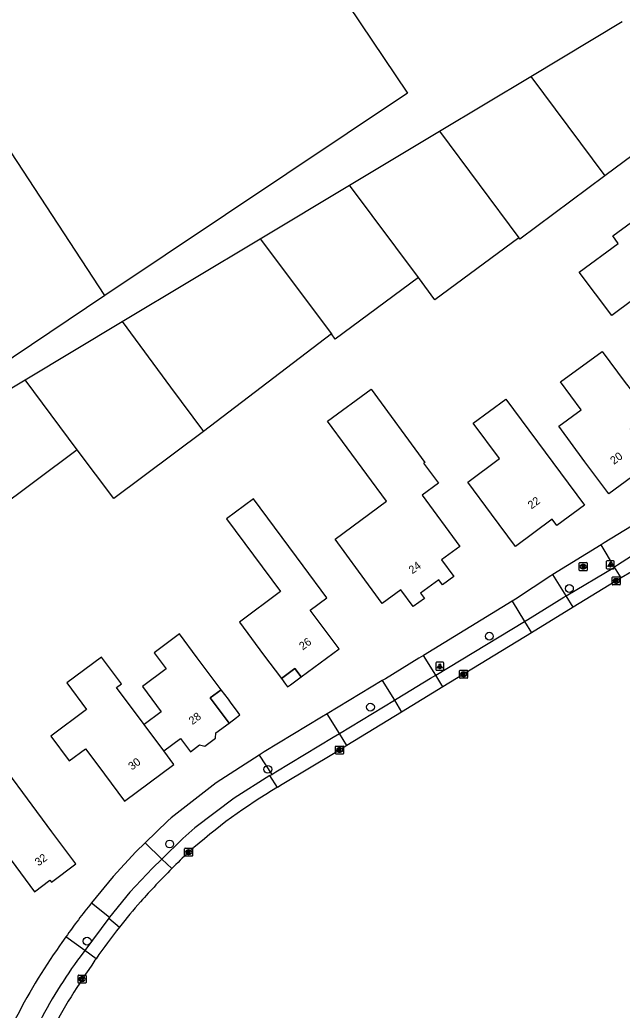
# Model space of a CAD drawing. Extents: x 156651 to 158072, y 387631 to 388990.
# Drawn here: x 157423.6 to 157498.9, y 387781.5 to 387905.3 of the extents above; entities that cross this region are included whole.
import ezdxf

# ---------------------------------------------------------------- set-up
doc = ezdxf.new("R2010")
doc.units = 0
for name, color, linetype in [('IMGEO_Boom', 7, 'Continuous'), ('IMGEO_Brandkraan', 7, 'Continuous'), ('IMGEO_Kolk', 7, 'Continuous'), ('IMGEO_Lichtpunt', 7, 'Continuous'), ('IMGEO_Pand', 7, 'Continuous'), ('IMGEO_Pand_nummerreeks', 7, 'Continuous'), ('IMGEO_Pand_overbouw', 7, 'Continuous'), ('IMGEO_Rijbaan_lokaal_open', 7, 'Continuous'), ('IMGEO_Voetpad_open', 7, 'Continuous')]:
    doc.layers.add(name, color=color, linetype=linetype)

msp = doc.modelspace()

# ---------------------------------------------------------------- linework, layer by layer
at = {"layer": 'IMGEO_Boom'}
for centre in [(157492.26, 387834.21), (157482.27, 387828.25), (157467.42, 387819.39), (157454.6, 387811.62), (157442.35, 387802.29), (157432.04, 387790.15)]:
    msp.add_circle(centre, 0.489, dxfattribs=at)
at = {"layer": 'IMGEO_Brandkraan'}
for p, q in [((157493.48, 387836.52), (157493.48, 387837.37)), ((157493.56, 387837.44), (157494.41, 387837.44)), ((157494.41, 387836.44), (157493.56, 387836.44)), ((157493.97, 387837.22), (157494, 387837.22)), ((157493.99, 387836.66), (157493.97, 387836.66)), ((157494.48, 387837.37), (157494.48, 387836.52))]:
    msp.add_line(p, q, dxfattribs=at)
for points in [[(157493.48, 387836.52), (157493.48, 387837.37)], [(157493.56, 387837.44), (157494.41, 387837.44)], [(157494.41, 387836.44), (157493.56, 387836.44)], [(157493.83, 387837.14), (157493.83, 387836.74), (157494.04, 387836.74)], [(157494.06, 387837.14), (157493.83, 387837.14)], [(157494.01, 387837.06), (157493.96, 387837.06), (157493.96, 387836.98)], [(157493.96, 387836.98), (157494.01, 387836.98)], [(157494.02, 387836.91), (157493.96, 387836.91), (157493.96, 387836.83)], [(157493.96, 387836.83), (157494.02, 387836.83)], [(157494.48, 387837.37), (157494.48, 387836.52)]]:
    msp.add_lwpolyline(points, dxfattribs=at)
for centre, radius, start, end in [((157493.56, 387837.37), 0.0765, 91.552, 178.448), ((157493.56, 387837.37), 0.0765, 91.552, 178.448), ((157493.56, 387836.52), 0.0765, 181.552, 268.448), ((157493.56, 387836.52), 0.0765, 181.552, 268.448), ((157494.01, 387837.02), 0.0379, 267.8285, 90.9355), ((157494.02, 387836.87), 0.0404, 269.8759, 90.5077), ((157494.05, 387836.99), 0.251, 268.6676, 293.5347), ((157494.07, 387837), 0.145, 59.4692, 91.5367), ((157494.09, 387837.04), 0.0922, 285.5137, 58.1501), ((157494.1, 387836.85), 0.105, 301.3115, 78.989), ((157494.41, 387837.37), 0.0765, 1.552, 88.448), ((157494.41, 387837.37), 0.0765, 1.552, 88.448), ((157494.41, 387836.52), 0.0765, 271.552, 358.448), ((157494.41, 387836.52), 0.0765, 271.552, 358.448)]:
    msp.add_arc(centre, radius, start, end, dxfattribs=at)
for centre, major_axis, ratio, start_param, end_param in [((157493.97, 387836.94), (-0.387, 0.002), 0.722429, 4.712389, 7.853982), ((157493.99, 387836.94), (-0.39, 0.002), 0.717154, 1.570796, 4.712389)]:
    msp.add_ellipse(centre, major_axis=major_axis, ratio=ratio, start_param=start_param, end_param=end_param, dxfattribs=at)
at = {"layer": 'IMGEO_Kolk'}
for p, q in [((157497.62, 387834.74), (157497.62, 387835.59)), ((157497.69, 387835.67), (157498.54, 387835.67)), ((157498.11, 387835.44), (157498.13, 387835.44)), ((157498.62, 387835.59), (157498.62, 387834.74)), ((157498.54, 387834.66), (157497.69, 387834.66)), ((157498.13, 387834.89), (157498.1, 387834.89)), ((157478.55, 387823.08), (157478.55, 387823.93)), ((157478.63, 387824), (157479.48, 387824)), ((157479.55, 387823.93), (157479.55, 387823.08)), ((157479.48, 387823), (157478.63, 387823)), ((157479.04, 387823.78), (157479.06, 387823.78)), ((157479.06, 387823.22), (157479.04, 387823.22)), ((157463.07, 387813.61), (157463.07, 387814.46)), ((157463.14, 387814.53), (157463.99, 387814.53)), ((157463.55, 387814.31), (157463.58, 387814.31)), ((157464.07, 387814.46), (157464.07, 387813.61)), ((157463.99, 387813.53), (157463.14, 387813.53)), ((157463.58, 387813.75), (157463.55, 387813.75)), ((157444.22, 387800.85), (157444.22, 387801.7)), ((157444.3, 387801.77), (157445.15, 387801.77)), ((157445.22, 387801.7), (157445.22, 387800.85)), ((157445.15, 387800.77), (157444.3, 387800.77)), ((157444.71, 387801.55), (157444.73, 387801.55)), ((157444.73, 387800.99), (157444.71, 387800.99)), ((157430.91, 387784.99), (157430.91, 387785.84)), ((157430.98, 387785.91), (157431.83, 387785.91)), ((157431.39, 387785.69), (157431.42, 387785.69)), ((157431.91, 387785.84), (157431.91, 387784.99)), ((157431.83, 387784.91), (157430.98, 387784.91)), ((157431.42, 387785.13), (157431.39, 387785.13))]:
    msp.add_line(p, q, dxfattribs=at)
for points in [[(157497.62, 387834.74), (157497.62, 387835.59)], [(157497.69, 387835.67), (157498.54, 387835.67)], [(157497.94, 387835.36), (157498.06, 387835.36), (157498.06, 387835.21), (157498.19, 387835.36), (157498.36, 387835.36), (157498.21, 387835.21), (157498.36, 387834.96), (157498.21, 387834.96), (157498.13, 387835.13), (157498.06, 387835.06), (157498.06, 387834.96), (157497.94, 387834.96), (157497.94, 387835.36)], [(157498.62, 387835.59), (157498.62, 387834.74)], [(157498.54, 387834.66), (157497.69, 387834.66)], [(157478.55, 387823.08), (157478.55, 387823.93)], [(157478.63, 387824), (157479.48, 387824)], [(157479.55, 387823.93), (157479.55, 387823.08)], [(157479.48, 387823), (157478.63, 387823)], [(157478.87, 387823.7), (157479, 387823.7), (157479, 387823.55), (157479.12, 387823.7), (157479.29, 387823.7), (157479.14, 387823.55), (157479.3, 387823.3), (157479.14, 387823.3), (157479.06, 387823.47), (157479, 387823.4), (157479, 387823.3), (157478.87, 387823.3), (157478.87, 387823.7)], [(157463.07, 387813.61), (157463.07, 387814.46)], [(157463.14, 387814.53), (157463.99, 387814.53)], [(157463.39, 387814.23), (157463.51, 387814.23), (157463.51, 387814.08), (157463.64, 387814.23), (157463.8, 387814.23), (157463.66, 387814.08), (157463.81, 387813.83), (157463.66, 387813.83), (157463.57, 387814), (157463.51, 387813.93), (157463.51, 387813.83), (157463.39, 387813.83), (157463.39, 387814.23)], [(157464.07, 387814.46), (157464.07, 387813.61)], [(157463.99, 387813.53), (157463.14, 387813.53)], [(157444.22, 387800.85), (157444.22, 387801.7)], [(157444.3, 387801.77), (157445.15, 387801.77)], [(157445.22, 387801.7), (157445.22, 387800.85)], [(157445.15, 387800.77), (157444.3, 387800.77)], [(157444.54, 387801.47), (157444.67, 387801.47), (157444.67, 387801.32), (157444.79, 387801.47), (157444.96, 387801.47), (157444.81, 387801.32), (157444.97, 387801.07), (157444.81, 387801.07), (157444.73, 387801.24), (157444.67, 387801.17), (157444.67, 387801.07), (157444.54, 387801.07), (157444.54, 387801.47)], [(157430.91, 387784.99), (157430.91, 387785.84)], [(157430.98, 387785.91), (157431.83, 387785.91)], [(157431.23, 387785.61), (157431.35, 387785.61), (157431.35, 387785.46), (157431.48, 387785.61), (157431.64, 387785.61), (157431.5, 387785.46), (157431.65, 387785.21), (157431.5, 387785.21), (157431.41, 387785.38), (157431.35, 387785.31), (157431.35, 387785.21), (157431.23, 387785.21), (157431.23, 387785.61)], [(157431.91, 387785.84), (157431.91, 387784.99)], [(157431.83, 387784.91), (157430.98, 387784.91)]]:
    msp.add_lwpolyline(points, dxfattribs=at)
for centre, start, end in [((157497.69, 387835.59), 91.552, 178.448), ((157497.69, 387835.59), 91.552, 178.448), ((157498.54, 387835.59), 1.552, 88.448), ((157498.54, 387835.59), 1.552, 88.448), ((157497.69, 387834.74), 181.552, 268.448), ((157497.69, 387834.74), 181.552, 268.448), ((157498.54, 387834.74), 271.552, 358.448), ((157498.54, 387834.74), 271.552, 358.448), ((157478.63, 387823.93), 91.552, 178.448), ((157478.63, 387823.93), 91.552, 178.448), ((157479.48, 387823.93), 1.552, 88.448), ((157479.48, 387823.93), 1.552, 88.448), ((157478.63, 387823.08), 181.552, 268.448), ((157478.63, 387823.08), 181.552, 268.448), ((157479.48, 387823.08), 271.552, 358.448), ((157479.48, 387823.08), 271.552, 358.448), ((157463.14, 387814.46), 91.552, 178.448), ((157463.14, 387814.46), 91.552, 178.448), ((157463.99, 387814.46), 1.552, 88.448), ((157463.99, 387814.46), 1.552, 88.448), ((157463.14, 387813.61), 181.552, 268.448), ((157463.14, 387813.61), 181.552, 268.448), ((157463.99, 387813.61), 271.552, 358.448), ((157463.99, 387813.61), 271.552, 358.448), ((157444.3, 387801.7), 91.552, 178.448), ((157444.3, 387801.7), 91.552, 178.448), ((157445.15, 387801.7), 1.552, 88.448), ((157445.15, 387801.7), 1.552, 88.448), ((157444.3, 387800.85), 181.552, 268.448), ((157444.3, 387800.85), 181.552, 268.448), ((157445.15, 387800.85), 271.552, 358.448), ((157445.15, 387800.85), 271.552, 358.448), ((157430.98, 387785.84), 91.552, 178.448), ((157430.98, 387785.84), 91.552, 178.448), ((157431.83, 387785.84), 1.552, 88.448), ((157431.83, 387785.84), 1.552, 88.448), ((157430.98, 387784.99), 181.552, 268.448), ((157430.98, 387784.99), 181.552, 268.448), ((157431.83, 387784.99), 271.552, 358.448), ((157431.83, 387784.99), 271.552, 358.448)]:
    msp.add_arc(centre, 0.0765, start, end, dxfattribs=at)
for centre, major_axis, ratio, start_param, end_param in [((157498.1, 387835.16), (-0.387, 0.002), 0.722429, 4.712389, 7.853982), ((157498.13, 387835.16), (-0.39, 0.002), 0.717154, 1.570796, 4.712389), ((157479.04, 387823.5), (-0.387, 0.002), 0.722429, 4.712389, 7.853982), ((157479.06, 387823.5), (-0.39, 0.002), 0.717154, 1.570796, 4.712389), ((157463.55, 387814.03), (-0.387, 0.002), 0.722429, 4.712389, 7.853982), ((157463.58, 387814.03), (-0.39, 0.002), 0.717154, 1.570796, 4.712389), ((157444.71, 387801.27), (-0.387, 0.002), 0.722429, 4.712389, 7.853982), ((157444.73, 387801.27), (-0.39, 0.002), 0.717154, 1.570796, 4.712389), ((157431.39, 387785.41), (-0.387, 0.002), 0.722429, 4.712389, 7.853982), ((157431.42, 387785.41), (-0.39, 0.002), 0.717154, 1.570796, 4.712389)]:
    msp.add_ellipse(centre, major_axis=major_axis, ratio=ratio, start_param=start_param, end_param=end_param, dxfattribs=at)
at = {"layer": 'IMGEO_Lichtpunt'}
for p, q in [((157496.86, 387837.58), (157496.86, 387836.77)), ((157496.86, 387837.58), (157496.86, 387836.77)), ((157497.77, 387837.68), (157496.96, 387837.68)), ((157497.77, 387837.68), (157496.96, 387837.68)), ((157497.86, 387836.77), (157497.86, 387837.58)), ((157497.86, 387836.77), (157497.86, 387837.58)), ((157496.96, 387836.68), (157497.77, 387836.68)), ((157496.96, 387836.68), (157497.77, 387836.68)), ((157475.58, 387824.89), (157475.58, 387824.09)), ((157475.58, 387824.89), (157475.58, 387824.09)), ((157476.49, 387824.99), (157475.68, 387824.99)), ((157476.49, 387824.99), (157475.68, 387824.99)), ((157475.68, 387823.99), (157476.49, 387823.99)), ((157475.68, 387823.99), (157476.49, 387823.99)), ((157476.58, 387824.09), (157476.58, 387824.89)), ((157476.58, 387824.09), (157476.58, 387824.89))]:
    msp.add_line(p, q, dxfattribs=at)
for points in [[(157497.24, 387837.24), (157497.28, 387837.22), (157497.09, 387836.95), (157497.05, 387836.98), (157497.24, 387837.24)], [(157497.34, 387837.2), (157497.39, 387837.2), (157497.39, 387836.87), (157497.34, 387836.87), (157497.34, 387837.2)], [(157497.45, 387837.22), (157497.49, 387837.24), (157497.67, 387836.98), (157497.64, 387836.95), (157497.45, 387837.22)], [(157475.96, 387824.56), (157476, 387824.53), (157475.81, 387824.27), (157475.77, 387824.29), (157475.96, 387824.56)], [(157476.06, 387824.51), (157476.11, 387824.51), (157476.11, 387824.19), (157476.06, 387824.19), (157476.06, 387824.51)], [(157476.17, 387824.53), (157476.21, 387824.56), (157476.39, 387824.29), (157476.36, 387824.27), (157476.17, 387824.53)]]:
    msp.add_lwpolyline(points, dxfattribs=at)
for centre in [(157497.36, 387837.38), (157476.08, 387824.69)]:
    msp.add_circle(centre, 0.0994, dxfattribs=at)
for centre, start, end in [((157496.96, 387837.58), 90, 180), ((157496.96, 387837.58), 90, 180), ((157497.77, 387837.58), 0, 90), ((157497.77, 387837.58), 0, 90), ((157496.96, 387836.77), 180, 270), ((157496.96, 387836.77), 180, 270), ((157497.77, 387836.77), 270, 0), ((157497.77, 387836.77), 270, 360), ((157475.68, 387824.89), 90, 180), ((157475.68, 387824.89), 90, 180), ((157475.68, 387824.09), 180, 270), ((157475.68, 387824.09), 180, 270), ((157476.49, 387824.89), 0, 90), ((157476.49, 387824.89), 0, 90), ((157476.49, 387824.09), 270, 0), ((157476.49, 387824.09), 270, 360)]:
    msp.add_arc(centre, 0.0946, start, end, dxfattribs=at)
at = {"layer": 'IMGEO_Pand'}
for points in [[(157446.96, 387933.45), (157472.05, 387896.09), (157434.24, 387870.82)], [(157434.24, 387870.82), (157409.42, 387908.81)], [(157487.44, 387898.19), (157498.86, 387905.05)], [(157476.04, 387891.35), (157487.44, 387898.19)], [(157487.44, 387898.19), (157496.7, 387885.76)], [(157507.31, 387893.66), (157496.7, 387885.76)], [(157464.82, 387884.61), (157476.04, 387891.35)], [(157476.04, 387891.35), (157485.94, 387878.04)], [(157453.64, 387877.91), (157464.82, 387884.61)], [(157473.4, 387873.07), (157464.82, 387884.61)], [(157496.7, 387885.76), (157486.07, 387877.86), (157485.94, 387878.04)], [(157500, 387879.97), (157500.65, 387880.45), (157513.38, 387863.36), (157516.36, 387859.35), (157508.54, 387853.53), (157502.31, 387861.9), (157501.54, 387862.92), (157503.54, 387864.37), (157506.6, 387863.76), (157508.57, 387865.29), (157507.77, 387867.43), (157507.48, 387868.08), (157506.51, 387869.44), (157505.67, 387870.37), (157504.42, 387871.38), (157503.12, 387872.02), (157502.62, 387872.09), (157497.54, 387868.3), (157493.49, 387873.73), (157498.37, 387877.33), (157497.69, 387878.26), (157500, 387879.97)], [(157436.4, 387867.55), (157453.64, 387877.91)], [(157453.64, 387877.91), (157462.54, 387866.01)], [(157485.94, 387878.04), (157475.47, 387870.29), (157473.4, 387873.07)], [(157473.4, 387873.07), (157463.03, 387865.36), (157462.54, 387866.01)], [(157434.24, 387870.82), (157415.88, 387858.5)], [(157424.32, 387860.3), (157436.4, 387867.55)], [(157436.4, 387867.55), (157442.47, 387859.36), (157446.57, 387853.84)], [(157462.54, 387866.01), (157446.57, 387853.84)], [(157493.74, 387856.55), (157491.16, 387860.02), (157496.36, 387863.84), (157499.24, 387859.96), (157500, 387858.94), (157502.22, 387855.95), (157500, 387854.25), (157499.83, 387854.12), (157500, 387853.89), (157502.79, 387850.2), (157500, 387848.13), (157497.17, 387846.03), (157494.2, 387850.05), (157490.94, 387854.48), (157493.74, 387856.55)], [(157413.11, 387853.57), (157424.32, 387860.3)], [(157430.82, 387851.55), (157424.32, 387860.3)], [(157474.22, 387849.97), (157474.06, 387849.86), (157475.9, 387847.36), (157473.86, 387845.86), (157478.56, 387839.47), (157476.28, 387837.79), (157477.82, 387835.7), (157476.41, 387834.66), (157475.95, 387835.29), (157473.68, 387833.61), (157474.15, 387832.98), (157472.76, 387831.95), (157471.2, 387834.05), (157468.89, 387832.35), (157465.93, 387836.38), (157463, 387840.37), (157469.44, 387845.13), (157462.05, 387855.12), (157467.49, 387859.13), (157474.22, 387849.97)], [(157491.16, 387848.65), (157494.14, 387844.63), (157490.69, 387842.08), (157490.11, 387842.87), (157485.51, 387839.46), (157482.53, 387843.48), (157479.56, 387847.49), (157483.54, 387850.44), (157480.26, 387854.87), (157484.32, 387857.88), (157491.16, 387848.65)], [(157446.57, 387853.84), (157435.38, 387845.46), (157430.82, 387851.55)], [(157430.82, 387851.55), (157420.35, 387843.75)], [(157459.01, 387837.06), (157452.81, 387845.41), (157450.56, 387843.73), (157449.45, 387842.9), (157456.19, 387833.83), (157451.05, 387830.01), (157454.08, 387825.94), (157456.3, 387822.96), (157457.98, 387824.22), (157458.76, 387823.17), (157463.5, 387826.67), (157459.9, 387831.49), (157461.99, 387833.04), (157459.01, 387837.06)], [(157441.62, 387813.94), (157443.71, 387815.49), (157444.94, 387813.81), (157446.09, 387814.66), (157446.73, 387814.52), (157448.07, 387815.53), (157448.13, 387816.19), (157449.77, 387817.4), (157447.42, 387820.55), (157448.77, 387821.55), (157445.8, 387825.56), (157443.59, 387828.54), (157440.42, 387826.19), (157441.91, 387824.18), (157438.94, 387821.97), (157441.28, 387818.79), (157439.17, 387817.22)], [(157439.17, 387817.22), (157435.71, 387821.86), (157436.32, 387822.31), (157433.83, 387825.65), (157429.49, 387822.42), (157431.98, 387819.08), (157427.53, 387815.76), (157429.82, 387812.69), (157431.83, 387814.19), (157433.37, 387812.12), (157436.72, 387807.64), (157442.89, 387812.24), (157441.62, 387813.94)], [(157441.62, 387813.94), (157439.17, 387817.22)], [(157416.52, 387807.02), (157419.04, 387803.79), (157419.61, 387804.22), (157425.46, 387796.32), (157427.4, 387797.77), (157427.58, 387797.53), (157430.64, 387799.81), (157427.65, 387803.82), (157419.05, 387815.39), (157413.55, 387811.3)]]:
    msp.add_lwpolyline(points, dxfattribs=at)
at = {"layer": 'IMGEO_Pand_overbouw'}
for points in [[(157456.3, 387822.96), (157456.8, 387822.28), (157457.07, 387821.93), (157457.42, 387822.19), (157458.76, 387823.17), (157457.98, 387824.22)], [(157449.77, 387817.4), (157450.68, 387818.1), (157451.11, 387818.42), (157450.92, 387818.7), (157449.94, 387820.01), (157449.69, 387820.37), (157448.77, 387821.55), (157447.42, 387820.55)]]:
    msp.add_lwpolyline(points, close=True, dxfattribs=at)
at = {"layer": 'IMGEO_Rijbaan_lokaal_open'}
for points in [[(157504.77, 387839.23), (157500, 387836.31), (157498.72, 387835.53)], [(157498.72, 387835.53), (157492.72, 387831.86)], [(157492.72, 387831.86), (157487.52, 387828.68)], [(157487.52, 387828.68), (157476.47, 387821.92)], [(157476.47, 387821.92), (157471.31, 387818.77)], [(157471.31, 387818.77), (157464.47, 387814.58)], [(157464.47, 387814.58), (157463, 387813.68), (157456.38, 387809.71), (157455.81, 387809.37)]]:
    msp.add_lwpolyline(points, dxfattribs=at)
for centre, radius, start, end in [((157491.6, 387748.76), 70.39, 120.5572, 131.7521), ((157510.62, 387731.73), 95.81, 133.4591, 135.2201), ((157514.29, 387727.9), 101.11, 135.1457, 138.3646), ((157498.73, 387742.52), 79.77, 138.785, 141.7462), ((157499.38, 387742.02), 80.59, 141.7536, 145.2442), ((157492.23, 387745.23), 72.87, 144.8866, 153.3467), ((157498.42, 387742.71), 79.41, 145.26, 145.9691)]:
    msp.add_arc(centre, radius, start, end, dxfattribs=at)
at = {"layer": 'IMGEO_Voetpad_open'}
for points in [[(157502.09, 387843.33), (157500.69, 387842.43), (157500, 387842), (157496.62, 387839.9), (157496.21, 387839.65)], [(157503.8, 387840.71), (157502.34, 387839.77), (157500, 387838.25), (157498.27, 387837.12), (157497.89, 387836.89)], [(157496.21, 387839.65), (157490.2, 387835.98)], [(157497.89, 387836.89), (157496.21, 387839.65)], [(157491.85, 387833.28), (157497.89, 387836.89)], [(157498.72, 387835.53), (157497.89, 387836.89)], [(157490.2, 387835.98), (157489.93, 387835.81), (157485.54, 387832.9), (157485.11, 387832.62)], [(157491.85, 387833.28), (157490.2, 387835.98)], [(157485.11, 387832.62), (157474.06, 387825.86)], [(157485.11, 387832.62), (157486.65, 387830.1)], [(157486.65, 387830.1), (157487.07, 387830.35), (157491.58, 387833.11), (157491.85, 387833.28)], [(157492.72, 387831.86), (157491.85, 387833.28)], [(157475.57, 387823.39), (157486.65, 387830.1)], [(157486.65, 387830.1), (157487.52, 387828.68)], [(157474.06, 387825.86), (157473.47, 387825.5), (157469.28, 387822.93), (157468.9, 387822.71)], [(157475.57, 387823.39), (157474.06, 387825.86)], [(157468.9, 387822.71), (157462.03, 387818.57)], [(157468.9, 387822.71), (157470.41, 387820.25)], [(157470.41, 387820.25), (157470.77, 387820.47), (157474.93, 387823), (157475.57, 387823.39)], [(157476.47, 387821.92), (157475.57, 387823.39)], [(157463.54, 387816.1), (157470.41, 387820.25)], [(157470.41, 387820.25), (157471.31, 387818.77)], [(157462.03, 387818.57), (157461.29, 387818.13), (157454.13, 387813.79), (157453.54, 387813.4)], [(157463.54, 387816.1), (157462.03, 387818.57)], [(157455.11, 387810.99), (157455.62, 387811.31), (157462.78, 387815.64), (157463.54, 387816.1)], [(157464.47, 387814.58), (157463.54, 387816.1)], [(157453.54, 387813.4), (157448.15, 387809.93), (157442.54, 387805.55), (157442.11, 387805.17), (157439.29, 387802.43)], [(157453.54, 387813.4), (157455.11, 387810.99)], [(157454.86, 387810.83), (157450.4, 387808.03), (157445.49, 387804.29), (157443.99, 387802.99), (157441.38, 387800.41)], [(157454.86, 387810.83), (157455.11, 387810.99)], [(157455.81, 387809.37), (157454.86, 387810.83)], [(157439.29, 387802.43), (157438.14, 387801.31), (157435.31, 387798.21), (157432.57, 387794.93)], [(157441.38, 387800.41), (157439.29, 387802.43)], [(157441.38, 387800.41), (157440.22, 387799.28), (157437.37, 387796.26), (157434.82, 387793.14)], [(157442.62, 387799.21), (157441.38, 387800.41)], [(157432.57, 387794.93), (157434.82, 387793.14)], [(157434.74, 387793.02), (157431.75, 387788.98)], [(157434.82, 387793.14), (157434.74, 387793.02)], [(157434.74, 387793.02), (157436.09, 387791.91)], [(157429.39, 387790.69), (157428.89, 387789.98), (157428.6, 387789.57)], [(157431.75, 387788.98), (157429.39, 387790.69)], [(157431.75, 387788.98), (157431.16, 387788.18), (157430.86, 387787.77)], [(157433.17, 387787.96), (157431.75, 387788.98)]]:
    msp.add_lwpolyline(points, dxfattribs=at)
for centre, radius, start, end in [((157505.52, 387736.81), 93.27, 141.4583, 144.711), ((157487.5, 387747.86), 72.17, 144.6992, 153.5028), ((157478.38, 387753.22), 58.76, 143.9802, 154.0158)]:
    msp.add_arc(centre, radius, start, end, dxfattribs=at)

# ---------------------------------------------------------------- texts
at = {"layer": 'IMGEO_Pand_nummerreeks'}
for s, rotation, p in [('20', 36.6422, (157497.82, 387849.65)), ('22', 36.5018, (157487.52, 387844.08)), ('24', 36.524, (157472.65, 387835.98)), ('26', 36.4401, (157458.96, 387826.46)), ('28', 36.6808, (157445.19, 387817.14)), ('30', 36.7381, (157437.64, 387811.46)), ('32', 36.6407, (157425.97, 387799.48))]:
    msp.add_text(s, height=1, rotation=rotation, dxfattribs=at).set_placement(p)

doc.saveas('drawing.dxf')
